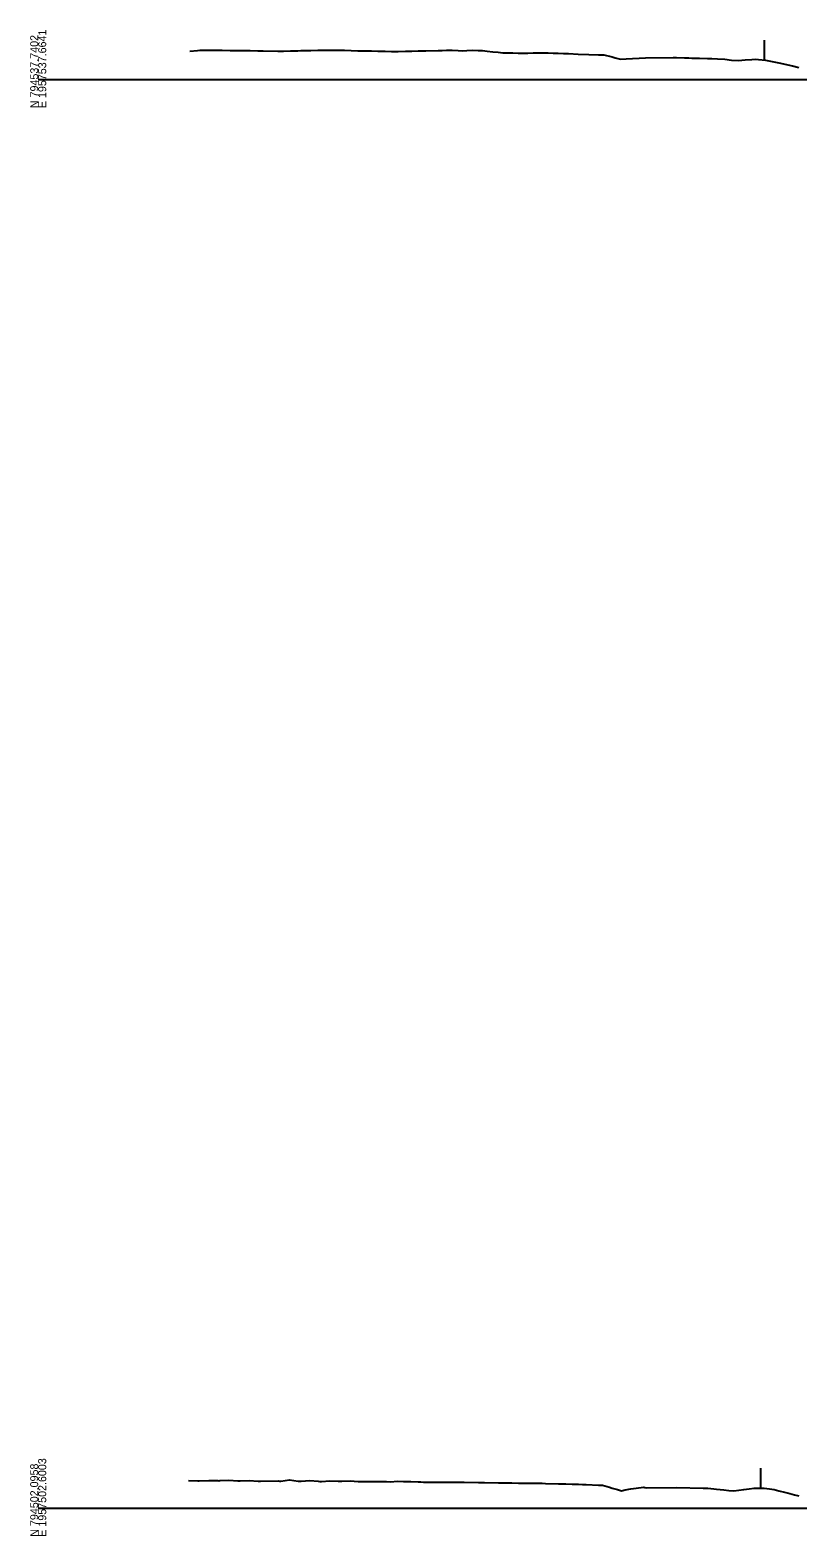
# Model space of a CAD drawing. Extents: x -4026 to 9638, y -10 to 19609.
# Drawn here: x -3003 to -2734, y 13990 to 14517 of the extents above; entities that cross this region are included whole.
import ezdxf

# ---------------------------------------------------------------- set-up
doc = ezdxf.new("R2010")
doc.units = 0
for name, color, linetype in [('Default', 7, 'Continuous'), ('RD_EX_Fence_Other', 7, 'Continuous'), ('RD_GPK_XS_Cell', 7, 'Continuous'), ('RD_XS_ExGround', 7, 'Continuous')]:
    doc.layers.add(name, color=color, linetype=linetype)

msp = doc.modelspace()

# ---------------------------------------------------------------- linework, layer by layer
at = {"layer": 'RD_EX_Fence_Other'}
for p, q in [((-2745.88, 14513.81), (-2745.88, 14506.81)), ((-2747.12, 14014.02), (-2747.12, 14007.02))]:
    msp.add_line(p, q, dxfattribs=at)
at = {"layer": 'RD_GPK_XS_Cell'}
for p, q in [((-3000, 14500), (-2650, 14500)), ((-3000, 14000), (-2650, 14000))]:
    msp.add_line(p, q, dxfattribs=at)
at = {"layer": 'RD_XS_ExGround'}
for points in [[(-2946.98, 14509.98), (-2944.19, 14510.22), (-2943.45, 14510.28), (-2942.69, 14510.29), (-2937.18, 14510.27), (-2936.38, 14510.26), (-2935.56, 14510.24), (-2932.84, 14510.19), (-2930.16, 14510.13), (-2929.3, 14510.11), (-2928.43, 14510.13), (-2925.77, 14510.2), (-2923.15, 14510.1), (-2922.23, 14510.06), (-2921.3, 14510.05), (-2916.14, 14509.96), (-2915.16, 14509.93), (-2914.17, 14509.96), (-2911.63, 14510.02), (-2909.12, 14510.08), (-2908.09, 14510.11), (-2907.04, 14510.14), (-2904.55, 14510.2), (-2902.11, 14510.24), (-2901.02, 14510.26), (-2899.91, 14510.26), (-2897.48, 14510.27), (-2895.09, 14510.29), (-2893.95, 14510.29), (-2892.78, 14510.25), (-2890.41, 14510.15), (-2888.08, 14510.09), (-2886.88, 14510.05), (-2885.65, 14510.04), (-2883.34, 14510.03), (-2881.07, 14509.95), (-2878.52, 14509.88), (-2876.27, 14509.85), (-2874.05, 14509.86), (-2871.39, 14509.9), (-2869.2, 14509.96), (-2867.04, 14510.01), (-2865.66, 14510.04), (-2864.26, 14510.07), (-2860.03, 14510.14), (-2858.59, 14510.19), (-2857.13, 14510.25), (-2855.06, 14510.32), (-2853.01, 14510.17), (-2851.52, 14510.06), (-2850, 14510.17), (-2847.98, 14510.29), (-2846, 14510.21), (-2844.45, 14510.16), (-2842.87, 14509.95), (-2840.91, 14509.72), (-2838.98, 14509.54), (-2837.38, 14509.37), (-2835.74, 14509.35), (-2833.84, 14509.33), (-2831.97, 14509.29), (-2830.31, 14509.26), (-2828.61, 14509.27), (-2826.77, 14509.3), (-2824.96, 14509.3), (-2823.23, 14509.32), (-2821.48, 14509.31), (-2819.7, 14509.29), (-2817.94, 14509.21), (-2816.16, 14509.14), (-2814.35, 14509.07), (-2810.93, 14508.93), (-2807.22, 14508.75), (-2803.92, 14508.65), (-2802.02, 14508.61), (-2799.12, 14507.91), (-2798.03, 14507.64), (-2796.21, 14507.19), (-2794.15, 14507.29), (-2787.45, 14507.59), (-2777.75, 14507.68), (-2776.59, 14507.69), (-2773.81, 14507.61), (-2772.23, 14507.55), (-2771.17, 14507.52), (-2770.4, 14507.49), (-2769.83, 14507.47), (-2769.37, 14507.46), (-2768.47, 14507.43), (-2765.7, 14507.36), (-2764.21, 14507.32), (-2762.19, 14507.26), (-2759.59, 14507.18), (-2757.31, 14506.79), (-2754.82, 14506.71), (-2752.52, 14506.93), (-2750.18, 14507.04), (-2748.99, 14507.09), (-2747.81, 14507.01), (-2745.45, 14506.77), (-2743.05, 14506.32), (-2741.91, 14506.09), (-2740.79, 14505.86), (-2735.92, 14504.85), (-2733.78, 14504.25)], [(-2947.39, 14009.69), (-2944.1, 14009.62), (-2943.61, 14009.62), (-2940.32, 14009.69), (-2937.09, 14009.64), (-2936.79, 14009.63), (-2936.48, 14009.64), (-2933.25, 14009.8), (-2930.07, 14009.58), (-2929.71, 14009.56), (-2929.35, 14009.58), (-2926.18, 14009.74), (-2923.06, 14009.49), (-2922.22, 14009.48), (-2916.05, 14009.52), (-2915.57, 14009.49), (-2915.09, 14009.51), (-2912.04, 14009.94), (-2909.03, 14009.46), (-2908.5, 14009.43), (-2907.96, 14009.47), (-2904.96, 14009.67), (-2902.02, 14009.43), (-2901.43, 14009.39), (-2900.83, 14009.39), (-2897.89, 14009.57), (-2895.01, 14009.42), (-2894.36, 14009.42), (-2893.7, 14009.42), (-2890.82, 14009.54), (-2887.99, 14009.39), (-2887.29, 14009.36), (-2885.86, 14009.34), (-2885.22, 14009.35), (-2883.55, 14009.34), (-2880.55, 14009.35), (-2880.11, 14009.34), (-2879.54, 14009.36), (-2879.14, 14009.35), (-2878.09, 14009.31), (-2876.68, 14009.22), (-2874.21, 14009.4), (-2872.11, 14009.31), (-2869.61, 14009.29), (-2866.95, 14009.19), (-2866.07, 14009.17), (-2865.18, 14009.15), (-2859.94, 14009.08), (-2858.05, 14009.08), (-2852.92, 14009.06), (-2850.92, 14009.05), (-2845.91, 14009.01), (-2843.79, 14008.97), (-2838.9, 14008.88), (-2836.66, 14008.85), (-2834.25, 14008.85), (-2831.88, 14008.8), (-2829.53, 14008.75), (-2827.18, 14008.74), (-2824.87, 14008.71), (-2823.64, 14008.7), (-2822.4, 14008.68), (-2817.85, 14008.56), (-2816.57, 14008.53), (-2815.27, 14008.51), (-2813.04, 14008.45), (-2810.84, 14008.4), (-2809.5, 14008.34), (-2808.14, 14008.28), (-2803.83, 14008.11), (-2802.43, 14008.06), (-2799.96, 14007.31), (-2799.07, 14007.06), (-2797.18, 14006.56), (-2795.83, 14006.13), (-2794.5, 14006.42), (-2792.5, 14006.77), (-2788.01, 14007.38), (-2787.59, 14007.25), (-2787.14, 14007.1), (-2776.43, 14007.21), (-2767.25, 14006.99), (-2765.6, 14006.95), (-2763.45, 14006.75), (-2762.57, 14006.67), (-2760, 14006.43), (-2758.23, 14006.22), (-2756.47, 14006.02), (-2754.73, 14006.26), (-2752.93, 14006.51), (-2751.1, 14006.73), (-2749.4, 14006.95), (-2747.72, 14007), (-2745.86, 14007.05), (-2743.97, 14006.77), (-2742.32, 14006.53), (-2740.7, 14006.1), (-2738.79, 14005.59), (-2736.84, 14005.11), (-2735.25, 14004.73), (-2733.69, 14004.38)]]:
    msp.add_lwpolyline(points, dxfattribs=at)

# ---------------------------------------------------------------- texts
at = {"layer": 'Default'}
for p in [(-3000, 14500), (-3000, 14000)]:
    msp.add_text('-', height=0.0001, dxfattribs=at).set_placement(p)
at = {"layer": 'RD_GPK_XS_Cell'}
for s, p in [('N 794537.7402', (-3000, 14490)), ('E 1957537.6641', (-2997.2, 14490)), ('N 794502.0958', (-3000, 13990)), ('E 1957502.6003', (-2997.2, 13990))]:
    msp.add_text(s, height=2.8, rotation=90, dxfattribs=at).set_placement(p)

doc.saveas('drawing.dxf')
